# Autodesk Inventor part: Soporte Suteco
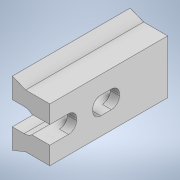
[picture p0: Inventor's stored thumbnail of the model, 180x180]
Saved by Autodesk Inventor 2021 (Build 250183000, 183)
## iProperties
Created: 2021-03
Part Number: Soporte Suteco
Material: Genérico
Document SubType Name: Modeling
Designer: ATOUZA
Density: 1 g/cm^3
Appearance: Valor por defecto
Author: ATOUZA
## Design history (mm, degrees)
sketch "Boceto1"
  geometry: L1 (0.791, -1.4)-(1.963, -1.4) reference; L2 (1.963, -1.4)-(1.963, 1.4) reference; L3 (1.963, 1.4)-(0.791, 1.4) reference; L4 (0.873, -1.6)-(2.163, -1.6); L5 (2.163, -1.6)-(2.163, 1.6); L6 (2.163, 1.6)-(0.873, 1.6); L7 (2.163, 1.6)-(0.723, 1.6); L8 (2.163, -1.6)-(0.723, -1.6); L9 (2.163, -1.6)-(2.163, 1.6); L10 (-2.837, 2.2)-(-2.837, 6); L11 (-2.837, 6)-(-0.337, 5); L12 (-0.337, 5)-(4.163, 5); L13 (4.163, 5)-(4.163, 1.673); L14 (-2.837, 2.2)-(-0.637, 2.2); L15 (0.791, 1.673)-(4.163, 1.673); L16 (-2.637, 0)-(1.963, 0); L17 (-2.837, -2.2)-(-0.637, -2.2); L18 (-2.837, -2.2)-(-2.837, -6); L19 (-2.837, -6)-(-0.337, -5); L20 (-0.337, -5)-(4.163, -5); L21 (4.163, -5)-(4.163, -1.673); L22 (0.791, -1.673)-(4.163, -1.673); A1 r 2 centre (-0.637, 0) between (0.791, 1.4) and (0.791, -1.4) reference; A2 r 2.1 centre (-0.637, 0) between (0.723, 1.6) and (0.723, -1.6); A3 r 2.2 centre (-0.637, 0) between (0.873, 1.6) and (0.873, -1.6); A4 r 2.2 centre (-0.637, 0) between (0.791, 1.673) and (-0.637, 2.2); A5 r 2.2 centre (-0.637, 0) between (0.873, 1.6) and (0.873, -1.6); A6 r 2.2 centre (-0.637, 0) between (0.873, 1.6) and (0.873, -1.6); A7 r 2.2 centre (-0.637, 0) between (0.873, 1.6) and (0.873, -1.6); A8 r 2.2 centre (-0.637, 0) between (0.873, 1.6) and (0.873, -1.6); A9 r 2.2 centre (-0.637, 0) between (-0.637, -2.2) and (0.791, -1.673); 1 further point; 1 other entity
  constraints: 38 end point, 21 point on circle, 16 symmetric about line, 8 centre point, 3 coincident, 2 perpendicular, 2 point on line, 1 horizontal, 1 midpoint, 1 parallel, 1 tangent, 10 other
  dimensions: "d0" = 4.2 diameter of A2; "d1" = 0.2 distance between parallel lines of L3 L6; "d3" = 5 distance between parallel lines of L16 L12; "d4" = 2.5 horizontal distance of L10.end L11.end; "d6" = 7 distance between parallel lines of L13 L10; "d12" = 2.2 distance from line of L18 A1.centre; "d13" = 2 distance between parallel lines of L21 L5 (derived); "d14" = 6 distance from line of L16 L10.end
  node "Referencia1"
node "Plano de trabajo1"
extrude "Extrusión1" new body sketch "Boceto1" stored distance "d7" = 10; taper "d8" = 0 deg
sketch "Boceto2"
  geometry: L1 (1.501, -0.75)-(2.924, -2.173) reference; L2 (2.499, -2.597)-(1.076, -1.174) reference; L3 (7, -2.073)-(7, -1.273) reference; L4 (9.6, -2.473)-(7.4, -2.473) reference; L5 (10, -1.273)-(10, -2.073) reference; L6 (7.4, -0.873)-(9.6, -0.873) reference; L7 (7, -2.073)-(7, -1.273) reference; L8 (7.4, -0.873)-(9.6, -0.873) reference; L9 (10, -1.273)-(10, -2.073) reference; L10 (9.6, -2.473)-(7.4, -2.473) reference; L11 (0, -3.073)-(0, -0.273) reference; L12 (0, -3.073)-(22, -3.073) reference; L13 (22, -0.273)-(22, -3.073) reference; L14 (0, -0.273)-(22, -0.273) reference; L15 (0, 0)-(22, 0) reference; L16 (0, -3.347)-(22, -3.347) reference; L17 (5, 0)-(8, 0); L18 (8, 0)-(8, -3.347); L19 (8, -3.347)-(5, -3.347); L20 (5, -3.347)-(5, 0); L21 (22, -6.673)-(22, -3.347) reference; L22 (13, 0)-(22, 0); L23 (22, 0)-(22, -3.347); L24 (22, -3.347)-(13, -3.347); L25 (13, -3.347)-(13, 0); C1 r 1.25 at (2, -1.673) reference; C2 r 1.25 at (2, -1.673) reference; A1 r 1.05 centre (2, -1.673) between (2.924, -2.173) and (1.501, -0.75) reference; A2 r 1.05 centre (2, -1.673) between (1.076, -1.174) and (2.499, -2.597) reference; A3 r 0.4 centre (7.4, -2.073) between (7, -2.073) and (7.4, -2.473) reference; A4 r 0.4 centre (9.6, -2.073) between (9.6, -2.473) and (10, -2.073) reference; A5 r 0.4 centre (9.6, -1.273) between (10, -1.273) and (9.6, -0.873) reference; A6 r 0.4 centre (7.4, -1.273) between (7.4, -0.873) and (7, -1.273) reference; A7 r 0.4 centre (7.4, -2.073) between (7, -2.073) and (7.4, -2.473) reference; A8 r 0.4 centre (7.4, -1.273) between (7.4, -0.873) and (7, -1.273) reference; A9 r 0.4 centre (9.6, -1.273) between (10, -1.273) and (9.6, -0.873) reference; A10 r 0.4 centre (9.6, -2.073) between (9.6, -2.473) and (10, -2.073) reference; 6 further points
  constraints: 16 end point, 4 parallel, 3 point on line, 2 horizontal, 2 perpendicular
  dimensions: "d15" = 9 distance between parallel lines of L13 L25; "d16" = 5 distance between parallel lines of L18 L25; "d17" = 3 distance between parallel lines of L18 L20
extrude "Extrusión2" join sketch "Boceto2" distance "d9" = 1.7; taper "d10" = 0 deg
fillet "Empalme1" dims "d11" = 1.5
node "Sólido1"
node "Referencia2"
node "Referencia3"
node "Referencia4"
